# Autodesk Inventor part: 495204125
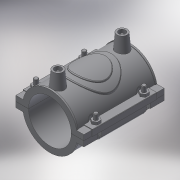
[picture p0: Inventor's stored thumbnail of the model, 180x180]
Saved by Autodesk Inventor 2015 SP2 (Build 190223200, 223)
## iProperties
Created: 2017-07
Part Number: 495204125
Material: Generic
Description: PLASSON REPAIR SADDLE 125
Document SubType Name: Modeling
Designer: KIM
Density: 1 g/cm^3
Appearance: Default
Author: KIM
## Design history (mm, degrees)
derived "495204.ipt"
feature "Solid1::495204.ipt"
tag "TaggingFeature1"
body "Solid1"
other parameters: "d0" = 125, "d1" = 147.5, "d2" = 162, "d3" = 31.25, "d4" = 118, "d5" = 0, "d6" = 0.1, "d8" = 0, "d19" = 6, "d20" = 6, "d21" = 70.8, "d23" = 0, "d24" = 35.4, "d26" = 0, "d27" = 3, "d28" = 3, "d29" = 3, "d30" = 41.66667, "d31" = 6, "d32" = 0, "d33" = 0, "d34" = 0.6, "d40" = 76.7, "d41" = 64.9, "d43" = 0, "d45" = 0, "d47" = 79.65, "d48" = 47.2, "d50" = 0, "d70" = 15, "d72" = 0, "d73" = 6, "d75" = 5, "d76" = 0, "d77" = 6.25, "d78" = 91.5, "d79" = 15, "d80" = 47.2, "d82" = 5 deg, "d84" = 4, "d85" = 14, "d86" = 0, "d87" = 3, "d88" = 0, "d89" = 1, "d90" = 1, "d91" = 94.4, "d92" = 0, "d93" = 0.5, "d94" = 65.78947, "d96" = 150.45, "d97" = 2.36, "d98" = 0, "d99" = 47.2, "d100" = 0, "d102" = 3.54, "d_" = 125, "B_" = 162, "H_" = 29, "L_" = 118, "d_t" = 6
